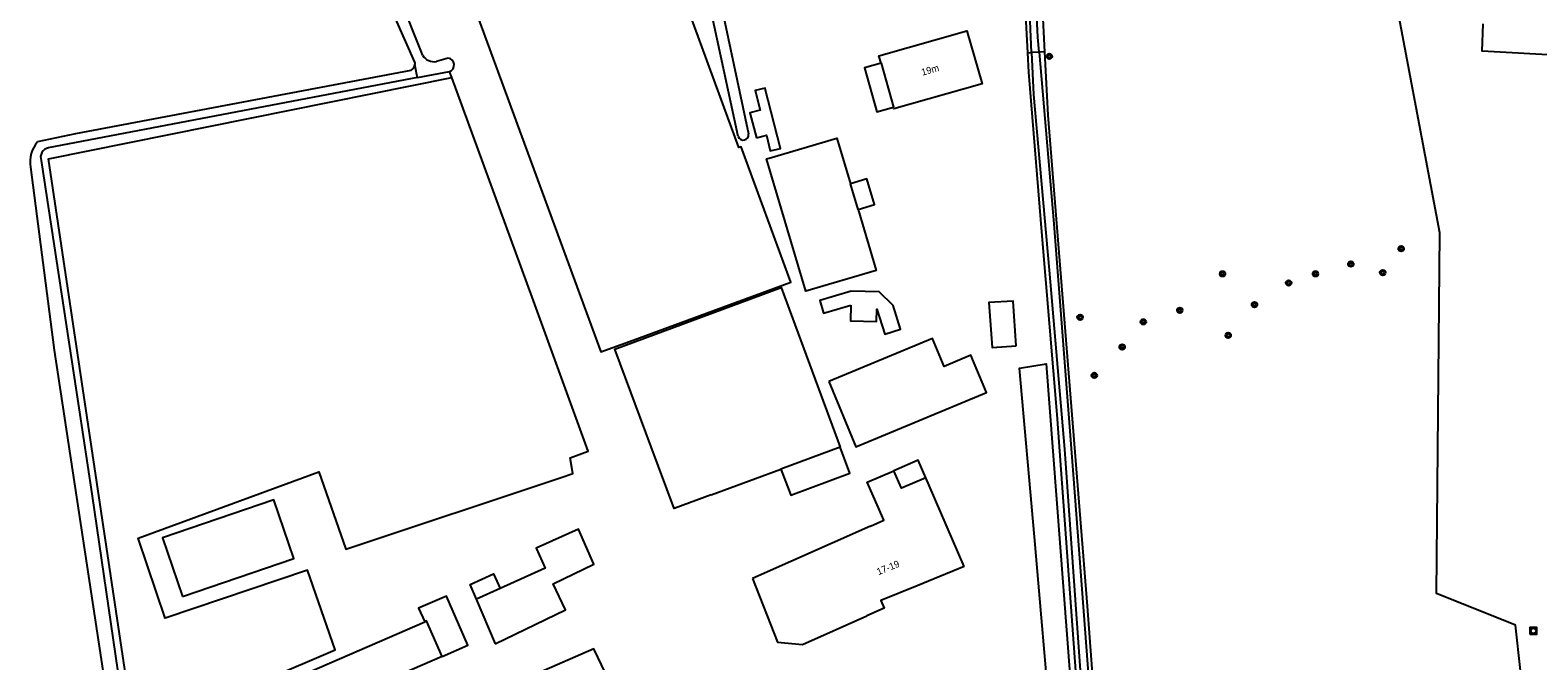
# Model space of a CAD drawing. Extents: x 141000 to 143000, y 400580 to 403500.
# Drawn here: x 141613.5 to 141831.6, y 403145 to 403236.3 of the extents above; entities that cross this region are included whole.
import ezdxf

# ---------------------------------------------------------------- set-up
doc = ezdxf.new("R2010")
doc.units = 0
for name, color, linetype in [('gg-afsc-erfafscheiding', 7, 'Continuous'), ('gg-anno-huisnummerreeks BGT', 7, 'Continuous'), ('gg-bbg-bijgebouw', 7, 'Continuous'), ('gg-bbg-hoofdgebouw', 7, 'Continuous'), ('gg-bbg-luifel en loopbrug', 7, 'Continuous'), ('gg-bbg-overig bouwwerk', 7, 'Continuous'), ('gg-knt-bronhoudergrens', 7, 'Continuous'), ('gg-knt-verharding', 7, 'Continuous'), ('gg-kntw-bovenkant insteek waterloop', 7, 'Continuous'), ('gg-kntw-waterlijn', 7, 'Continuous'), ('gt-grn-vlakafsluiter', 7, 'Continuous'), ('gt-symb-boom', 7, 'Continuous'), ('gt-symb-rioolschacht', 7, 'Continuous'), ('gx-grn-maaiveld', 7, 'Continuous')]:
    doc.layers.add(name, color=color, linetype=linetype)

# ---------------------------------------------------------------- blocks, each defined once
blk = doc.blocks.new('gt0-RS')
at = {"layer": 'gt-symb-rioolschacht'}
blk.add_lwpolyline([(-0.5, -0.5), (0.5, -0.5), (0.5, 0.5), (-0.5, 0.5)], close=True, dxfattribs=at)
blk.add_circle((0, 0), 0.375, dxfattribs=at)
blk = doc.blocks.new('gt0-BOOM')
at = {"layer": 'gt-symb-boom'}
for radius in [0.4, 0.2]:
    blk.add_circle((0, 0), radius, dxfattribs=at)

msp = doc.modelspace()

# ---------------------------------------------------------------- linework, layer by layer
at = {"layer": 'gg-afsc-erfafscheiding'}
msp.add_lwpolyline([(141829.12, 403143.58), (141828.41, 403150.13), (141816.98, 403154.75), (141817.48, 403206.91), (141809.8, 403247.58), (141805.45, 403245.95), (141796.22, 403275.03)], dxfattribs=at)
at = {"layer": 'gg-bbg-bijgebouw'}
for p, q in [((141733.27, 403210.3), (141732.17, 403214.01)), ((141730.7, 403175.92), (141722.11, 403172.74)), ((141712.04, 403169), (141722.11, 403172.74)), ((141681.5, 403155.47), (141678.07, 403153.92))]:
    msp.add_line(p, q, dxfattribs=at)
for points in [[(141671.56, 403321.4), (141650.49, 403313.73), (141666.11, 403271.29), (141696.05, 403189.69), (141700.74, 403191.41), (141711.33, 403195.29), (141723.55, 403199.77), (141716.35, 403219.36), (141716.04, 403219.25), (141706.76, 403244.61), (141709.78, 403245.71), (141702.52, 403265.55), (141705.53, 403266.65), (141699.37, 403283.49), (141697.21, 403289.15), (141700.18, 403290.29), (141686.85, 403326.96)], [(141733.27, 403210.3), (141735.89, 403201.49), (141725.73, 403198.47), (141720.05, 403217.61), (141720.43, 403217.72), (141730.21, 403220.62), (141732.17, 403214.01)], [(141703.34, 403175.97), (141698.1, 403190.1), (141722.14, 403199.01), (141730.7, 403175.92)], [(141729.06, 403185.39), (141732.97, 403175.96), (141751.86, 403183.81), (141749.61, 403189.22), (141745.72, 403187.6), (141744.05, 403191.62), (141729.06, 403185.39)], [(141712.04, 403169), (141706.66, 403167.01), (141703.34, 403175.97)], [(141635.55, 403154.3), (141651.62, 403159.79), (141648.75, 403168.29), (141632.65, 403162.79), (141635.55, 403154.3)], [(141680.77, 403147.45), (141690.97, 403152.38), (141689.16, 403156.12), (141695.05, 403158.97), (141692.82, 403164.04), (141686.7, 403161.28), (141688, 403158.39), (141681.5, 403155.47)], [(141678.07, 403153.92), (141678.04, 403153.91), (141680.77, 403147.45)], [(141673.08, 403145.62), (141642.64, 403132.39), (141640.43, 403137.54), (141670.57, 403150.63)], [(141673.08, 403145.62), (141670.85, 403150.76), (141670.57, 403150.63)]]:
    msp.add_lwpolyline(points, dxfattribs=at)
at = {"layer": 'gg-bbg-hoofdgebouw'}
for p, q in [((141736.6, 403231.47), (141738.4, 403225.11)), ((141735.09, 403164.47), (141718, 403156.9)), ((141744.27, 403156.86), (141741.82, 403155.86)), ((141748.63, 403158.64), (141744.27, 403156.86))]:
    msp.add_line(p, q, dxfattribs=at)
for points in [[(141834.07, 403278.36), (141836.96, 403278.24), (141836.92, 403277.43), (141835.07, 403237.57), (141834.8, 403232.58), (141823.57, 403233.19), (141823.73, 403237.19)], [(141736.6, 403231.47), (141736.3, 403232.55), (141749.04, 403236.16), (141751.22, 403228.47), (141738.47, 403224.86), (141738.4, 403225.11)], [(141735.09, 403164.47), (141737.01, 403165.32), (141736.22, 403167.12), (141734.62, 403170.84), (141738.46, 403172.49)], [(141743.08, 403171.49), (141739.55, 403169.97), (141738.46, 403172.49)], [(141748.63, 403158.64), (141743.57, 403170.36), (141743.08, 403171.49)], [(141718, 403156.9), (141721.6, 403147.67), (141725.23, 403147.34), (141734.57, 403151.49)], [(141741.82, 403155.86), (141736.57, 403153.72), (141737.07, 403152.6), (141734.57, 403151.49)], [(141673.07, 403126.74), (141683.85, 403131.43), (141684.18, 403130.66), (141699.52, 403137.35), (141695.07, 403146.73), (141669.27, 403135.48), (141673.07, 403126.74)]]:
    msp.add_lwpolyline(points, dxfattribs=at)
at = {"layer": 'gg-bbg-luifel en loopbrug'}
for points in [[(141736.6, 403231.47), (141734.19, 403230.79), (141735.99, 403224.43), (141738.4, 403225.11)], [(141718.56, 403220.68), (141720.01, 403221.04), (141720.58, 403218.78), (141722.04, 403219.15), (141719.86, 403227.78), (141719.84, 403227.88), (141718.38, 403227.51), (141719.1, 403224.68), (141717.64, 403224.31), (141718.56, 403220.68)], [(141733.27, 403210.3), (141735.67, 403211.02), (141734.57, 403214.72), (141732.17, 403214.01)], [(141756.15, 403190.57), (141755.71, 403197.05), (141752.21, 403196.82), (141752.66, 403190.33), (141756.15, 403190.57)], [(141722.11, 403172.74), (141723.53, 403168.98), (141732.09, 403172.15), (141730.7, 403175.92)], [(141743.08, 403171.49), (141741.99, 403174.02), (141738.46, 403172.49)], [(141678.07, 403153.92), (141677.15, 403156.05), (141680.52, 403157.6), (141681.5, 403155.47)], [(141673.08, 403145.62), (141676.82, 403147.24), (141673.71, 403154.36), (141669.7, 403152.63), (141670.57, 403150.63)]]:
    msp.add_lwpolyline(points, dxfattribs=at)
at = {"layer": 'gg-bbg-overig bouwwerk'}
msp.add_lwpolyline([(141732.24, 403196.48), (141732.18, 403194.19), (141735.96, 403194.1), (141736.01, 403195.9), (141737.15, 403192.27), (141739.44, 403192.99), (141738.36, 403196.42), (141736.33, 403198.38), (141732.29, 403198.48), (141727.73, 403197.14), (141728.26, 403195.31), (141732.24, 403196.48)], dxfattribs=at)
at = {"layer": 'gg-knt-bronhoudergrens'}
for points in [[(141654.73, 403102.94), (141634.94, 403091.76), (141616.15, 403217.64), (141674.51, 403229.38)], [(141654.73, 403102.94), (141642.73, 403130.14), (141640.91, 403129.3), (141637.23, 403137.84), (141657.61, 403146.59), (141653.62, 403158.13), (141633.01, 403151.17), (141629.1, 403162.73), (141655.24, 403172.36), (141659.18, 403161.13), (141690.34, 403171.52), (141691.99, 403172.11), (141691.61, 403174.34), (141694.24, 403175.31), (141686.11, 403197.59), (141674.51, 403229.38)]]:
    msp.add_lwpolyline(points, dxfattribs=at)
at = {"layer": 'gg-knt-verharding'}
for points in [[(141758.79, 403162.94), (141756.65, 403187.36), (141760.52, 403187.97), (141763.98, 403142.48), (141765.95, 403109.66), (141766.51, 403108.16)], [(141762.12, 403102.04), (141761.71, 403103.76), (141762.5, 403111.43), (141762.52, 403115.59), (141761.29, 403134.45), (141758.79, 403162.94)]]:
    msp.add_lwpolyline(points, dxfattribs=at)
at = {"layer": 'gg-kntw-bovenkant insteek waterloop'}
for p, q in [((141670.3, 403232.6), (141656.9, 403266.04)), ((141717.45, 403221.21), (141709.2, 403260.09)), ((141673.99, 403232.2), (141672.28, 403231.73)), ((141669.52, 403229.38), (141616.11, 403219.21)), ((141669.52, 403229.38), (141674.18, 403230.27)), ((141615.08, 403217.4), (141620.52, 403181.61))]:
    msp.add_line(p, q, dxfattribs=at)
for points in [[(141622.15, 403500), (141624.29, 403478.84), (141627.93, 403442.22), (141630.98, 403410.54), (141636.32, 403356.75), (141640.99, 403328.85), (141649.34, 403276.35), (141669.11, 403231.62), (141669.14, 403231.5), (141669.15, 403231.32)], [(141715.94, 403220.86), (141703, 403280.8), (141693.23, 403332.74)], [(141753.83, 403259.78), (141755.61, 403260.09), (141758.2, 403260.19), (141758.58, 403259.82), (141758.91, 403258.89), (141758.99, 403258.06), (141760.27, 403233.11)], [(141757.85, 403232.98), (141756.56, 403257.36), (141756.28, 403257.63), (141756.18, 403257.63), (141753.36, 403257.2), (141752.28, 403257.22), (141752.03, 403257.37), (141751.75, 403257.64), (141751.57, 403258.02), (141751.57, 403258.62), (141751.49, 403259.37)], [(141767.12, 403108.39), (141767.19, 403110.19), (141767.09, 403111.69), (141762.1, 403180.64), (141759.94, 403206.47), (141758, 403230.19), (141757.85, 403232.98)], [(141760.27, 403233.11), (141760.75, 403223.94), (141766.41, 403152.89), (141769.31, 403114.07), (141769.77, 403109.33)], [(141668.56, 403230.43), (141620.03, 403221.25), (141614.57, 403220.09)], [(141640.68, 403034.41), (141636.21, 403065.69), (141625.9, 403131.54), (141617, 403189.96), (141613.56, 403216.44)], [(141620.52, 403181.61), (141622.42, 403169.14), (141631.3, 403108.29), (141634.38, 403088.22)]]:
    msp.add_lwpolyline(points, dxfattribs=at)
for centre, radius, start, end in [((141668.15, 403231.35), 1, 293.8999, 358.5421), ((141671.9, 403233.55), 1.86, 210.7748, 281.7204), ((141673.84, 403231.21), 1, 290.0372, 81.2134), ((141716.67, 403221.12), 0.778, 199.8765, 6.596), ((141617.74, 403217.25), 4.26, 138.1905, 190.9833), ((141616.35, 403217.88), 1.35, 99.9704, 200.6285)]:
    msp.add_arc(centre, radius, start, end, dxfattribs=at)
at = {"layer": 'gg-kntw-waterlijn'}
for points in [[(141759.49, 403233.07), (141759.3, 403235.25), (141758.25, 403257.12), (141758.14, 403258.03), (141757.93, 403258.63), (141757.25, 403259.29), (141756.65, 403259.42), (141753.63, 403258.96), (141753.83, 403259.78)], [(141758.38, 403233.01), (141757.76, 403247.82), (141757.13, 403258.22), (141756.79, 403258.48), (141756.44, 403258.47), (141755.65, 403258.27), (141753.41, 403257.89), (141753.02, 403258.17), (141751.49, 403259.37)], [(141758.38, 403233.01), (141758.64, 403226.92), (141760.94, 403201.5), (141763.17, 403175.61), (141767.76, 403110.21), (141767.12, 403108.39)], [(141759.49, 403233.07), (141761.62, 403208.22), (141764.41, 403171.93), (141767.36, 403133.03), (141768.96, 403110.49), (141769.77, 403109.33)]]:
    msp.add_lwpolyline(points, dxfattribs=at)
at = {"layer": 'gt-grn-vlakafsluiter'}
msp.add_line((141759.49, 403233.07), (141758.38, 403233.01), dxfattribs=at)
msp.add_lwpolyline([(141669.52, 403229.38), (141669.44, 403229.8), (141669.15, 403231.32)], dxfattribs=at)
at = {"layer": 'gx-grn-maaiveld'}
for p, q in [((141757.85, 403232.98), (141758.38, 403233.01)), ((141760.27, 403233.11), (141759.49, 403233.07)), ((141674.51, 403229.38), (141674.18, 403230.27))]:
    msp.add_line(p, q, dxfattribs=at)

# ---------------------------------------------------------------- block references
at = {"layer": 'gt-symb-boom'}
for p in [(141760.95, 403232.46), (141811.87, 403204.62), (141804.58, 403202.4), (141786.02, 403200.99), (141799.46, 403200.99), (141809.2, 403201.16), (141795.59, 403199.67), (141790.64, 403196.54), (141765.4, 403194.7), (141774.55, 403194.04), (141779.83, 403195.72), (141786.84, 403192.09), (141771.5, 403190.41), (141767.46, 403186.29)]:
    msp.add_blockref('gt0-BOOM', p, dxfattribs=at)
at = {"layer": 'gt-symb-rioolschacht'}
msp.add_blockref('gt0-RS', (141831, 403149.33), dxfattribs=at)

# ---------------------------------------------------------------- texts
at = {"layer": 'gg-anno-huisnummerreeks BGT'}
for s, rotation, p in [('19m', 15.8, (141742.59, 403229.66)), ('17-19', 22.2, (141736.22, 403157.36))]:
    msp.add_text(s, height=1, rotation=rotation, dxfattribs=at).set_placement(p)

doc.saveas('drawing.dxf')
